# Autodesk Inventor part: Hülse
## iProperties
Created: 2007-01
Part Number: Hülse
Cost Center: 0 kg
Material: S235JRG2 (1.0038)
Document SubType Name: Modeling
Designer: M. Fiedler
Manufacturer: Standard
Standards Organization: Custom
Einheit: Stück
Ersatzteil: ET AB VT
Grundoberfläche: Rz6.3
WSK a+: 0
WSK a-: -0.1
WSK i+: +0.1
WSK i-: 0
SaveDate: 2007-01-25
SaveTime: 20:54
FileName: Hülse
Masse: 0 kg
Author: M. Fiedler
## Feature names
1. Drehung1 [Revolution]
2. Abgeleiteter Körper1 [Tagging]
